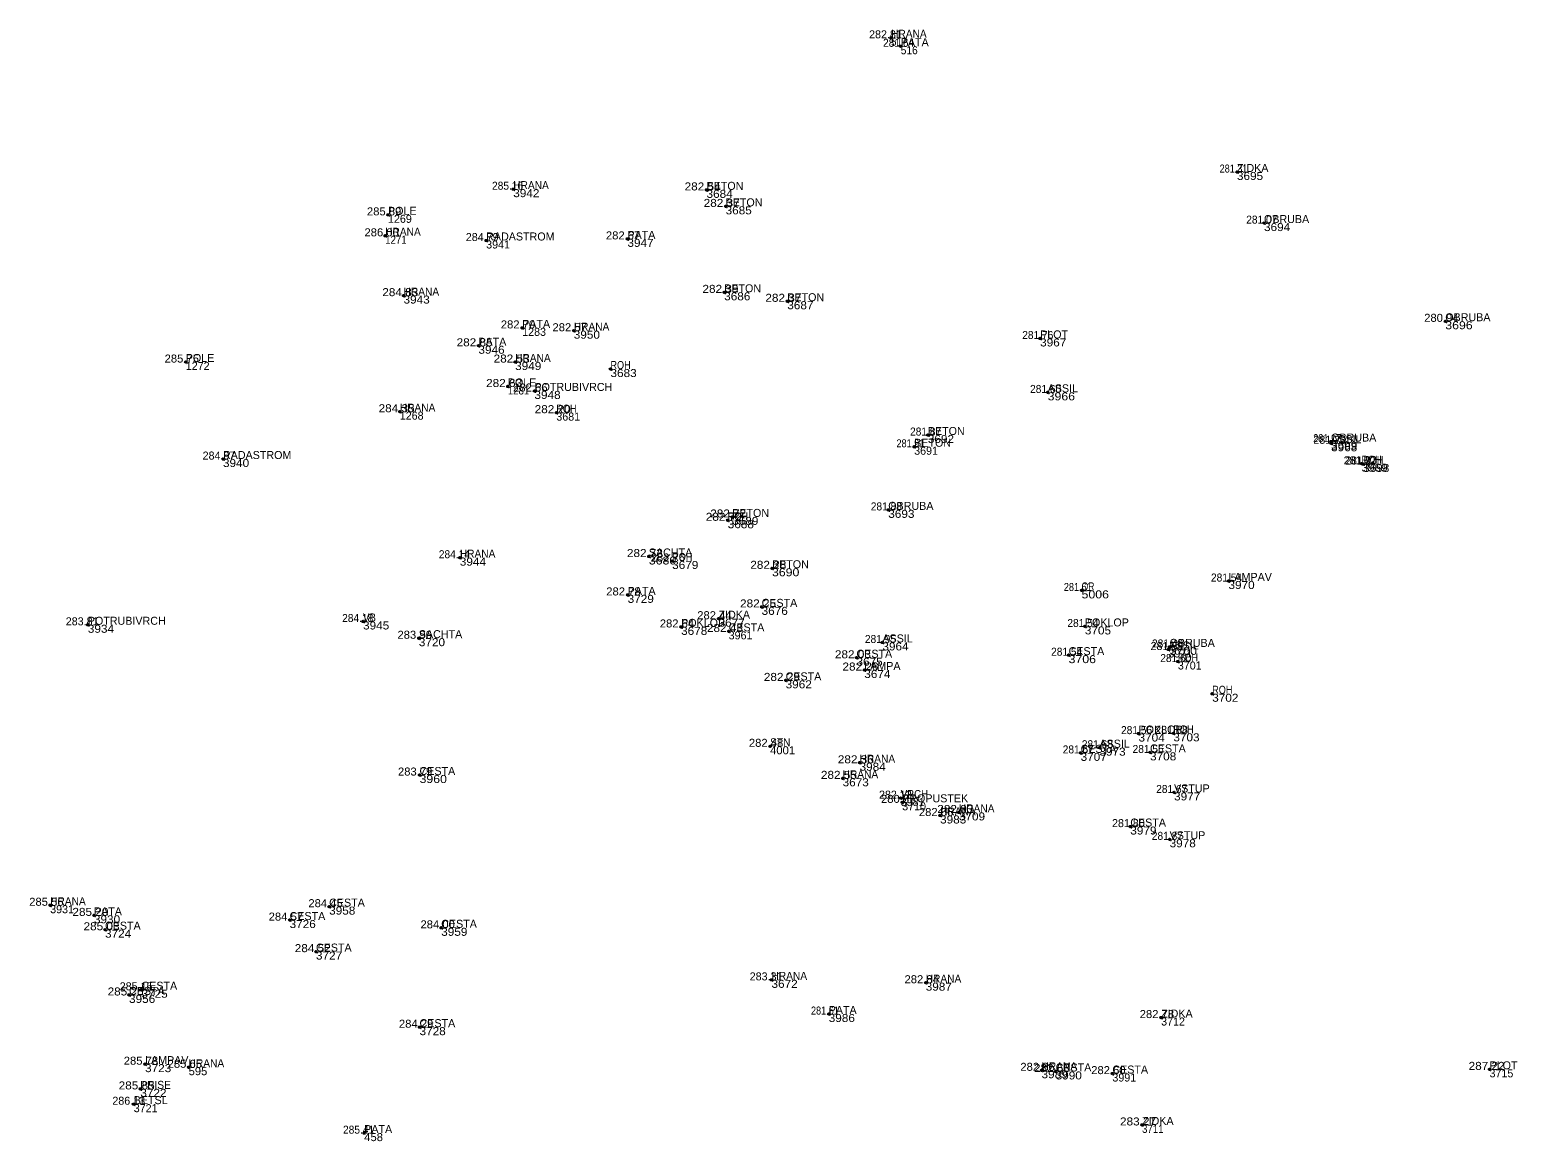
# Model space of a CAD drawing. Extents: x -565336 to -561834, y -1146819 to -1145270.
# Drawn here: x -563681.5 to -563618.3, y -1145804.6 to -1145757.4 of the extents above; entities that cross this region are included whole.
import ezdxf
from ezdxf.enums import TextEntityAlignment as Align

# ---------------------------------------------------------------- set-up
doc = ezdxf.new("R2010")
doc.units = 0
doc.header["$LTSCALE"] = 0.14
doc.header["$PDMODE"] = 32
doc.header["$PDSIZE"] = 0.07
for name, color, linetype in [('40', 7, 'Continuous'), ('43', 7, 'Continuous'), ('44', 7, 'Continuous'), ('45', 7, 'Continuous')]:
    doc.layers.add(name, color=color, linetype=linetype)

msp = doc.modelspace()

# ---------------------------------------------------------------- linework, layer by layer
at = {"layer": '40'}
for p in [(-563644.9, -1145757.78), (-563644.49, -1145758.14), (-563630.21, -1145763.48), (-563660.95, -1145764.21), (-563652.74, -1145764.24), (-563651.93, -1145764.94), (-563666.27, -1145765.3), (-563666.39, -1145766.19), (-563629.06, -1145765.65), (-563662.1, -1145766.39), (-563656.1, -1145766.32), (-563665.61, -1145768.73), (-563651.99, -1145768.59), (-563649.31, -1145768.97), (-563621.36, -1145769.82), (-563660.57, -1145770.1), (-563658.38, -1145770.22), (-563638.57, -1145770.55), (-563662.43, -1145770.86), (-563674.86, -1145771.55), (-563660.87, -1145771.55), (-563656.82, -1145771.85), (-563661.18, -1145772.59), (-563660.05, -1145772.78), (-563638.25, -1145772.84), (-563665.77, -1145773.66), (-563659.12, -1145773.7), (-563643.34, -1145774.65), (-563626.21, -1145774.93), (-563626.21, -1145775), (-563673.28, -1145775.67), (-563643.92, -1145775.15), (-563624.92, -1145775.87), (-563624.85, -1145775.88), (-563651.65, -1145778.13), (-563645.02, -1145777.83), (-563651.84, -1145778.27), (-563663.22, -1145779.86), (-563655.19, -1145779.81), (-563654.2, -1145780), (-563649.96, -1145780.31), (-563636.81, -1145781.25), (-563630.57, -1145780.85), (-563656.09, -1145781.44), (-563650.4, -1145781.95), (-563667.33, -1145782.57), (-563652.23, -1145782.45), (-563679.02, -1145782.71), (-563664.96, -1145783.28), (-563653.82, -1145782.8), (-563651.8, -1145782.99), (-563636.67, -1145782.78), (-563645.27, -1145783.46), (-563633.12, -1145783.76), (-563633.07, -1145783.65), (-563646.37, -1145784.11), (-563637.36, -1145784), (-563632.72, -1145784.27), (-563649.38, -1145785.07), (-563646.04, -1145784.63), (-563631.26, -1145785.64), (-563634.39, -1145787.33), (-563632.91, -1145787.32), (-563650.04, -1145787.87), (-563636.85, -1145788.15), (-563636.05, -1145787.93), (-563633.9, -1145788.13), (-563646.24, -1145788.57), (-563664.93, -1145789.09), (-563646.96, -1145789.23), (-563644.49, -1145790.07), (-563644.43, -1145790.25), (-563632.88, -1145789.83), (-563642.82, -1145790.81), (-563642.02, -1145790.68), (-563634.74, -1145791.28), (-563633.07, -1145791.82), (-563680.62, -1145794.62), (-563668.77, -1145794.68), (-563678.76, -1145795.05), (-563670.45, -1145795.25), (-563678.29, -1145795.66), (-563664.01, -1145795.58), (-563669.33, -1145796.59), (-563649.98, -1145797.79), (-563677.27, -1145798.43), (-563676.74, -1145798.21), (-563643.43, -1145797.91), (-563647.55, -1145799.24), (-563633.43, -1145799.39), (-563664.93, -1145799.8), (-563676.59, -1145801.37), (-563674.74, -1145801.5), (-563638.51, -1145801.63), (-563619.48, -1145801.59), (-563637.91, -1145801.68), (-563635.5, -1145801.77), (-563676.79, -1145802.42), (-563677.07, -1145803.07), (-563634.24, -1145803.95), (-563667.28, -1145804.3)]:
    msp.add_point(p, dxfattribs=at)

# ---------------------------------------------------------------- texts
at = {"layer": '43'}
for s, width, p in [('517', 0.9, (-563644.9, -1145758.12)), ('516', 0.95, (-563644.49, -1145758.48)), ('3695', 1.1, (-563630.21, -1145763.82)), ('3942', 1.1, (-563660.95, -1145764.55)), ('3684', 1.1, (-563652.74, -1145764.58)), ('3685', 1.1, (-563651.93, -1145765.28)), ('1271', 0.9, (-563666.39, -1145766.53)), ('3694', 1.1, (-563629.06, -1145765.99)), ('3947', 1.1, (-563656.1, -1145766.66)), ('3943', 1.1, (-563665.61, -1145769.07)), ('3686', 1.1, (-563651.99, -1145768.93)), ('3687', 1.1, (-563649.31, -1145769.31)), ('3696', 1.15, (-563621.36, -1145770.16)), ('3950', 1.1, (-563658.38, -1145770.56)), ('3967', 1.1, (-563638.57, -1145770.89)), ('3946', 1.1, (-563662.43, -1145771.2)), ('3949', 1.1, (-563660.87, -1145771.89)), ('3683', 1.1, (-563656.82, -1145772.19)), ('1281', 0.9, (-563661.18, -1145772.93)), ('3948', 1.1, (-563660.05, -1145773.12)), ('3966', 1.15, (-563638.25, -1145773.18)), ('3692', 1.1, (-563643.34, -1145774.99)), ('3699', 1.1, (-563626.21, -1145775.27)), ('3968', 1.1, (-563626.21, -1145775.34)), ('3940', 1.1, (-563673.28, -1145776.01)), ('3969', 1.1, (-563624.92, -1145776.21)), ('3698', 1.1, (-563624.85, -1145776.22)), ('3689', 1.1, (-563651.65, -1145778.47)), ('3693', 1.1, (-563645.02, -1145778.17)), ('3688', 1.1, (-563651.84, -1145778.61)), ('3944', 1.1, (-563663.22, -1145780.2)), ('3680', 1.15, (-563655.19, -1145780.15)), ('3679', 1.1, (-563654.2, -1145780.34)), ('3690', 1.15, (-563649.96, -1145780.65)), ('5006', 1.15, (-563636.81, -1145781.59)), ('3970', 1.1, (-563630.57, -1145781.19)), ('3729', 1.1, (-563656.09, -1145781.78)), ('3676', 1.1, (-563650.4, -1145782.29)), ('3945', 1.1, (-563667.33, -1145782.91)), ('3677', 1.1, (-563652.23, -1145782.79)), ('3934', 1.1, (-563679.02, -1145783.05)), ('3720', 1.1, (-563664.96, -1145783.62)), ('3678', 1.1, (-563653.82, -1145783.14)), ('3705', 1.1, (-563636.67, -1145783.12)), ('3964', 1.1, (-563645.27, -1145783.8)), ('3700', 1.15, (-563633.07, -1145783.99)), ('3675', 1.1, (-563646.37, -1145784.45)), ('3706', 1.15, (-563637.36, -1145784.34)), ('3962', 1.1, (-563649.38, -1145785.41)), ('3674', 1.1, (-563646.04, -1145784.97)), ('3702', 1.1, (-563631.26, -1145785.98)), ('3704', 1.1, (-563634.39, -1145787.67)), ('3703', 1.1, (-563632.91, -1145787.66)), ('4001', 1.05, (-563650.04, -1145788.21)), ('3707', 1.1, (-563636.85, -1145788.49)), ('3973', 1.1, (-563636.05, -1145788.27)), ('3708', 1.1, (-563633.9, -1145788.47)), ('3984', 1.1, (-563646.24, -1145788.91)), ('3960', 1.15, (-563664.93, -1145789.43)), ('3673', 1.1, (-563646.96, -1145789.57)), ('3977', 1.1, (-563632.88, -1145790.17)), ('3983', 1.1, (-563642.82, -1145791.15)), ('3709', 1.1, (-563642.02, -1145791.02)), ('3979', 1.1, (-563634.74, -1145791.62)), ('3978', 1.1, (-563633.07, -1145792.16)), ('3930', 1.1, (-563678.76, -1145795.39)), ('3726', 1.1, (-563670.45, -1145795.59)), ('3958', 1.1, (-563668.77, -1145795.02)), ('3724', 1.1, (-563678.29, -1145796)), ('3959', 1.1, (-563664.01, -1145795.92)), ('3727', 1.1, (-563669.33, -1145796.93)), ('3672', 1.1, (-563649.98, -1145798.13)), ('3956', 1.1, (-563677.27, -1145798.77)), ('3725', 1.1, (-563676.74, -1145798.55)), ('3987', 1.1, (-563643.43, -1145798.25)), ('3986', 1.1, (-563647.55, -1145799.58)), ('3728', 1.1, (-563664.93, -1145800.14)), ('3723', 1.1, (-563676.59, -1145801.71)), ('595', 1.05, (-563674.74, -1145801.84)), ('3989', 1.1, (-563638.51, -1145801.97)), ('3990', 1.1, (-563637.91, -1145802.02)), ('3722', 1.1, (-563676.79, -1145802.76)), ('3711', 0.9, (-563634.24, -1145804.29)), ('458', 1.05, (-563667.28, -1145804.64))]:
    msp.add_text(s, height=0.34, dxfattribs=dict(at, width=width)).set_placement(p)
for s, p in [('1269', (-563666.27, -1145765.64)), ('3941', (-563662.1, -1145766.73)), ('1283', (-563660.57, -1145770.44)), ('1272', (-563674.86, -1145771.89)), ('1268', (-563665.77, -1145774)), ('3681', (-563659.12, -1145774.04)), ('3691', (-563643.92, -1145775.49)), ('3961', (-563651.8, -1145783.33)), ('3971', (-563633.12, -1145784.1)), ('3701', (-563632.72, -1145784.61)), ('3981', (-563644.49, -1145790.41)), ('3710', (-563644.43, -1145790.59)), ('3931', (-563680.62, -1145794.96)), ('3712', (-563633.43, -1145799.73)), ('3715', (-563619.48, -1145801.93)), ('3991', (-563635.5, -1145802.11)), ('3721', (-563677.07, -1145803.41))]:
    msp.add_text(s, height=0.34, dxfattribs=at).set_placement(p)
at = {"layer": '44'}
for s, p in [('282.81', (-563645.1395, -1145757.804)), ('284.79', (-563662.269, -1145766.414)), ('281.23', (-563626.269, -1145775.024)), ('284.97', (-563673.449, -1145775.694)), ('281.32', (-563624.979, -1145775.894)), ('283.81', (-563679.2625, -1145782.734)), ('281.53', (-563633.1845, -1145783.784)), ('281.58', (-563632.988, -1145787.344)), ('282.12', (-563644.72, -1145790.094)), ('281.80', (-563634.8205, -1145791.304)), ('283.31', (-563650.2105, -1145797.814)), ('285.15', (-563676.9705, -1145798.234)), ('286.13', (-563677.283, -1145803.094))]:
    msp.add_text(s, height=0.34, dxfattribs=at).set_placement(p, align=Align.CENTER)
for s, width, p in [('281.64', 0.95, (-563644.581, -1145758.164)), ('281.31', 0.85, (-563630.3535, -1145763.504)), ('285.16', 0.95, (-563661.19, -1145764.234)), ('282.54', 1.1, (-563652.906, -1145764.264)), ('282.37', 1.1, (-563652.096, -1145764.964)), ('285.89', 1.05, (-563666.435, -1145765.324)), ('281.07', 0.95, (-563629.154, -1145765.674)), ('286.00', 1.05, (-563666.54, -1145766.214)), ('282.67', 1.05, (-563656.2835, -1145766.344)), ('284.83', 1.1, (-563665.748, -1145768.754)), ('282.39', 1.1, (-563652.148, -1145768.614)), ('282.37', 1.1, (-563649.476, -1145768.994)), ('282.70', 1.05, (-563660.748, -1145770.124)), ('282.57', 1.05, (-563658.554, -1145770.244)), ('280.94', 1.05, (-563621.526, -1145769.844)), ('282.85', 1.1, (-563662.5905, -1145770.884)), ('281.76', 0.95, (-563638.6695, -1145770.574)), ('285.75', 1.05, (-563675.029, -1145771.574)), ('282.53', 1.1, (-563661.0185, -1145771.574)), ('282.63', 1.1, (-563661.338, -1145772.614)), ('282.66', 1.05, (-563660.225, -1145772.804)), ('281.60', 0.95, (-563638.336, -1145772.864)), ('284.35', 1.1, (-563665.904, -1145773.684)), ('282.20', 1.1, (-563659.275, -1145773.724)), ('281.87', 0.95, (-563643.434, -1145774.674)), ('281.91', 0.85, (-563644.081, -1145775.174)), ('281.17', 0.85, (-563626.379, -1145774.954)), ('281.27', 0.95, (-563624.9345, -1145775.904)), ('281.88', 0.95, (-563645.102, -1145777.854)), ('282.72', 1.1, (-563652.0085, -1145778.294)), ('282.72', 1.1, (-563651.8185, -1145778.154)), ('282.73', 1.1, (-563655.356, -1145779.834)), ('284.14', 0.95, (-563663.4505, -1145779.884)), ('282.76', 1.05, (-563654.3835, -1145780.024)), ('282.28', 1.1, (-563650.1165, -1145780.334)), ('281.54', 0.95, (-563630.652, -1145780.874)), ('282.78', 1.05, (-563656.2695, -1145781.464)), ('281.61', 0.85, (-563636.971, -1145781.274)), ('282.25', 1.1, (-563650.551, -1145781.974)), ('284.18', 0.95, (-563667.5565, -1145782.594)), ('282.64', 1.05, (-563653.995, -1145782.824)), ('282.44', 1.05, (-563652.405, -1145782.474)), ('281.54', 0.95, (-563636.752, -1145782.804)), ('283.96', 1.05, (-563665.138, -1145783.304)), ('282.43', 1.1, (-563651.958, -1145783.014)), ('281.95', 0.95, (-563645.352, -1145783.484)), ('282.03', 1.1, (-563646.5225, -1145784.134)), ('281.54', 0.95, (-563637.442, -1145784.024)), ('281.48', 0.95, (-563633.157, -1145783.674)), ('282.26', 1.1, (-563646.2005, -1145784.654)), ('281.60', 0.95, (-563632.806, -1145784.294)), ('282.29', 1.1, (-563649.5405, -1145785.094)), ('281.56', 0.95, (-563634.472, -1145787.354)), ('282.48', 1.05, (-563650.211, -1145787.894)), ('281.68', 0.95, (-563636.137, -1145787.954)), ('282.36', 1.1, (-563646.398, -1145788.594)), ('281.67', 0.95, (-563636.9495, -1145788.174)), ('281.56', 0.95, (-563633.982, -1145788.154)), ('283.79', 1.05, (-563665.1165, -1145789.114)), ('282.55', 1.1, (-563647.1165, -1145789.254)), ('281.67', 0.95, (-563632.9795, -1145789.854)), ('280.87', 1.05, (-563644.599, -1145790.274)), ('282.06', 1.05, (-563642.99, -1145790.834)), ('282.03', 1.1, (-563642.1725, -1145790.704)), ('281.87', 0.95, (-563633.164, -1145791.844)), ('285.56', 1.05, (-563680.781, -1145794.644)), ('284.45', 1.05, (-563668.9215, -1145794.704)), ('285.20', 1.1, (-563678.91, -1145795.074)), ('284.57', 1.05, (-563670.6095, -1145795.274)), ('284.00', 1.05, (-563664.16, -1145795.604)), ('285.03', 1.1, (-563678.4375, -1145795.684)), ('284.52', 1.1, (-563669.4665, -1145796.614)), ('282.84', 1.05, (-563643.6, -1145797.934)), ('285.25', 1.1, (-563677.416, -1145798.454)), ('281.61', 0.85, (-563647.711, -1145799.264)), ('282.78', 1.05, (-563633.6095, -1145799.414)), ('284.29', 1.05, (-563665.076, -1145799.824)), ('285.78', 1.05, (-563676.7645, -1145801.394)), ('285.65', 1.05, (-563674.901, -1145801.524)), ('282.86', 1.05, (-563638.68, -1145801.654)), ('282.63', 1.1, (-563638.068, -1145801.704)), ('282.60', 1.05, (-563635.67, -1145801.794)), ('287.22', 1.1, (-563619.6035, -1145801.614)), ('285.85', 1.1, (-563676.9455, -1145802.444)), ('285.41', 0.95, (-563667.52, -1145804.324)), ('283.27', 1.1, (-563634.4115, -1145803.974))]:
    msp.add_text(s, height=0.34, dxfattribs=dict(at, width=width)).set_placement(p, align=Align.CENTER)
at = {"layer": '45'}
for s, width, p in [('HRANA', 0.95, (-563644.9, -1145757.78)), ('HRANA', 0.95, (-563660.95, -1145764.21)), ('HRANA', 0.95, (-563666.39, -1145766.19)), ('HRANA', 0.95, (-563665.61, -1145768.73)), ('HRANA', 0.95, (-563658.38, -1145770.22)), ('HRANA', 0.95, (-563660.87, -1145771.55)), ('ROH', 0.85, (-563656.82, -1145771.85)), ('HRANA', 0.95, (-563665.77, -1145773.66)), ('ROH', 0.85, (-563659.12, -1145773.7)), ('ROH', 0.85, (-563624.92, -1145775.87)), ('ROH', 0.85, (-563624.85, -1145775.88)), ('ROH', 0.85, (-563651.84, -1145778.27)), ('HRANA', 0.95, (-563663.22, -1145779.86)), ('ROH', 0.85, (-563654.2, -1145780)), ('OR', 0.8, (-563636.81, -1145781.25)), ('VB', 0.9, (-563667.33, -1145782.57)), ('ROH', 0.85, (-563632.72, -1145784.27)), ('ROH', 0.85, (-563631.26, -1145785.64)), ('ROH', 0.85, (-563632.91, -1145787.32)), ('STN', 0.95, (-563650.04, -1145787.87)), ('HRANA', 0.95, (-563646.24, -1145788.57)), ('HRANA', 0.95, (-563646.96, -1145789.23)), ('VRCH', 0.9, (-563644.49, -1145790.07)), ('HRANA', 0.95, (-563642.82, -1145790.81)), ('HRANA', 0.95, (-563642.02, -1145790.68)), ('HRANA', 0.95, (-563680.62, -1145794.62)), ('HRANA', 0.95, (-563649.98, -1145797.79)), ('HRANA', 0.95, (-563643.43, -1145797.91)), ('HRANA', 0.95, (-563674.74, -1145801.5)), ('HRANA', 0.95, (-563638.51, -1145801.63)), ('PRISE', 0.95, (-563676.79, -1145802.42))]:
    msp.add_text(s, height=0.34, dxfattribs=dict(at, width=width)).set_placement(p)
for s, p in [('PATA', (-563644.49, -1145758.14)), ('ZIDKA', (-563630.21, -1145763.48)), ('BETON', (-563652.74, -1145764.24)), ('POLE', (-563666.27, -1145765.3)), ('BETON', (-563651.93, -1145764.94)), ('OBRUBA', (-563629.06, -1145765.65)), ('RADASTROM', (-563662.1, -1145766.39)), ('PATA', (-563656.1, -1145766.32)), ('BETON', (-563651.99, -1145768.59)), ('BETON', (-563649.31, -1145768.97)), ('PATA', (-563660.57, -1145770.1)), ('OBRUBA', (-563621.36, -1145769.82)), ('PATA', (-563662.43, -1145770.86)), ('PLOT', (-563638.57, -1145770.55)), ('POLE', (-563674.86, -1145771.55)), ('POLE', (-563661.18, -1145772.59)), ('POTRUBIVRCH', (-563660.05, -1145772.78)), ('ASSIL', (-563638.25, -1145772.84)), ('BETON', (-563643.34, -1145774.65)), ('BETON', (-563643.92, -1145775.15)), ('ASSIL', (-563626.21, -1145775)), ('OBRUBA', (-563626.21, -1145774.93)), ('RADASTROM', (-563673.28, -1145775.67)), ('OBRUBA', (-563645.02, -1145777.83)), ('BETON', (-563651.65, -1145778.13)), ('SACHTA', (-563655.19, -1145779.81)), ('BETON', (-563649.96, -1145780.31)), ('LAMPAV', (-563630.57, -1145780.85)), ('PATA', (-563656.09, -1145781.44)), ('CESTA', (-563650.4, -1145781.95)), ('POTRUBIVRCH', (-563679.02, -1145782.71)), ('POKLOP', (-563653.82, -1145782.8)), ('ZIDKA', (-563652.23, -1145782.45)), ('CESTA', (-563651.8, -1145782.99)), ('POKLOP', (-563636.67, -1145782.78)), ('SACHTA', (-563664.96, -1145783.28)), ('ASSIL', (-563645.27, -1145783.46)), ('CESTA', (-563646.37, -1145784.11)), ('CESTA', (-563637.36, -1145784)), ('ASSIL', (-563633.12, -1145783.76)), ('OBRUBA', (-563633.07, -1145783.65)), ('LAMPA', (-563646.04, -1145784.63)), ('CESTA', (-563649.38, -1145785.07)), ('POKLOP', (-563634.39, -1145787.33)), ('ASSIL', (-563636.05, -1145787.93)), ('CESTA', (-563636.85, -1145788.15)), ('CESTA', (-563633.9, -1145788.13)), ('CESTA', (-563664.93, -1145789.09)), ('VSTUP', (-563632.88, -1145789.83)), ('PROPUSTEK', (-563644.43, -1145790.25)), ('CESTA', (-563634.74, -1145791.28)), ('VSTUP', (-563633.07, -1145791.82)), ('CESTA', (-563668.77, -1145794.68)), ('PATA', (-563678.76, -1145795.05)), ('CESTA', (-563670.45, -1145795.25)), ('CESTA', (-563664.01, -1145795.58)), ('CESTA', (-563678.29, -1145795.66)), ('CESTA', (-563669.33, -1145796.59)), ('CESTA', (-563677.27, -1145798.43)), ('CESTA', (-563676.74, -1145798.21)), ('PATA', (-563647.55, -1145799.24)), ('ZIDKA', (-563633.43, -1145799.39)), ('CESTA', (-563664.93, -1145799.8)), ('LAMPAV', (-563676.59, -1145801.37)), ('CESTA', (-563637.91, -1145801.68)), ('CESTA', (-563635.5, -1145801.77)), ('PLOT', (-563619.48, -1145801.59)), ('BETSL', (-563677.07, -1145803.07)), ('PATA', (-563667.28, -1145804.3)), ('ZIDKA', (-563634.24, -1145803.95))]:
    msp.add_text(s, height=0.34, dxfattribs=at).set_placement(p)

doc.saveas('drawing.dxf')
